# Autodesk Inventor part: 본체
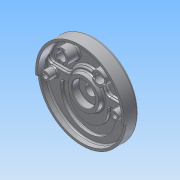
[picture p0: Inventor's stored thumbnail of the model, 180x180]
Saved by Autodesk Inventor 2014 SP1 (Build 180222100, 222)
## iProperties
Created: 2015-05
Part Number: 본체
Material: 알루미늄 6061
Document SubType Name: Modeling
Designer: 상담실
Density: 2.71 g/cm^3
Appearance: 알루미늄 - 평지
Mass: 1082.91 g
Surface Area: 1042.06 cm^2
Volume: 399.598 cm^3
Author: 상담실
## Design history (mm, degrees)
sketch "스케치1"
  geometry: C1 r 95 at (0, 0); 1 further point
  constraints: 1 centre point, 1 coincident
  dimensions: "d0" = 190 diameter of C1
extrude "돌출1" new body sketch "스케치1" distance "d1" = 32; taper "d2" = 0 deg
sketch "스케치2"
  geometry: C1 r 95 at (0, 0) reference; C2 r 90 at (0, 0)
  constraints: 1 centre point, 1 coincident
  dimensions: "d3" = 180 diameter of C2
extrude "돌출2" cut sketch "스케치2" distance "d4" = 25; taper "d5" = 0 deg
sketch "스케치3"
  geometry: L1 (-94.638, -8.28)-(-89.658, -7.844); L2 (89.658, -7.844)-(94.638, -8.28); L3 (-95, 0)-(95, 0); A1 r 90 centre (0, 0) between (-89.658, -7.844) and (89.658, -7.844) reference; A2 r 95 centre (0, 0) between (-94.638, -8.28) and (94.638, -8.28) reference; 2 further points
  constraints: 6 end point, 6 point on circle, 2 midpoint, 2 point on line, 1 coincident, 1 horizontal
  dimensions: "d6" = 5 deg angle of L3 L1; "d7" = 5 deg angle of L2 L3
extrude "돌출3" cut sketch "스케치3" distance "d8" = 5; taper "d9" = 0 deg
sketch "스케치4"
  geometry: L1 (-89.196, 12)-(-40.249, 12); L2 (40.249, 12)-(89.196, 12); A1 r 90 centre (0, 0) between (-89.196, 12) and (89.196, 12) reference; A2 r 42 centre (0, 0) between (40.249, 12) and (-40.249, 12)
  constraints: 4 end point, 4 point on circle, 2 horizontal, 1 centre point, 1 coincident, 1 collinear
  dimensions: "d10" = 84 diameter of A2; "d11" = 12 distance from line of A1.centre L1
extrude "돌출4" join sketch "스케치4" distance "d12" = 7; taper "d13" = 0 deg
sketch "스케치5"
  geometry: C1 r 35 at (0, 0); A1 r 42 centre (0, 0) between (40.249, 12) and (-40.249, 12) reference
  constraints: 1 centre point, 1 coincident
  dimensions: "d14" = 70 diameter of C1
extrude "돌출5" join sketch "스케치5" distance "d15" = 10; taper "d16" = -10 deg
sketch "스케치6"
  geometry: C1 r 95 at (0, 0) reference; C2 r 25 at (0, 0)
  constraints: 1 centre point, 1 coincident
  dimensions: "d17" = 50 diameter of C2
extrude "돌출6" join sketch "스케치6" distance "d18" = 12; taper "d19" = -15 deg
hole "구멍1" diameter "d22" = 23; stored, may be unused: countersink angle "d26" = 90 deg, drill point angle "d28" = 118 deg; dims "d20" = 10, "d21" = 10, "d23" = 6, "d24" = 4, "d25" = 2, "d27" = 8
fillet "모깎기1" dims "d31" = 10
fillet "모깎기2" dims "d32" = 3
fillet "모깎기3" dims "d33" = 5
sketch "스케치7"
  geometry: C1 r 9 at (-74, 0); C2 r 9 at (74, 0); A1 r 87 centre (0, 0) between (-86.059, 12.759) and (86.059, 12.759) reference
  constraints: 2 centre point, 2 horizontal alignment
  dimensions: "d34" = 18 diameter of C1; "d35" = 18 diameter of C2; "d36" = 148 distance of C2.centre C1.centre; "d37" = 74 distance of A1.centre C1.centre (= 0.5 x d36)
extrude "돌출7" join sketch "스케치7" distance "d38" = 18; taper "d39" = 0 deg
hole "구멍2" diameter "d42" = 11; stored, may be unused: countersink angle "d46" = 90 deg, drill point angle "d48" = 118 deg; dims "d40" = 10, "d41" = 10, "d43" = 6, "d44" = 4, "d45" = 2, "d47" = 8
hole "구멍3" diameter "d51" = 11; stored, may be unused: countersink angle "d55" = 90 deg, drill point angle "d57" = 118 deg; dims "d49" = 10, "d50" = 10, "d52" = 6, "d53" = 4, "d54" = 2, "d56" = 8
hole "구멍4" diameter "d60" = 18; stored, may be unused: countersink angle "d64" = 90 deg, drill point angle "d66" = 0 deg; dims "d61" = 6, "d62" = 4, "d63" = 2, "d65" = 11, "d67" = 10, "d68" = 10
hole "구멍5" diameter "d71" = 18; stored, may be unused: countersink angle "d75" = 90 deg, drill point angle "d77" = 0 deg; dims "d69" = 10, "d70" = 10, "d72" = 6, "d73" = 4, "d74" = 2, "d76" = 11
sketch "스케치8"
  geometry: C1 r 15 at (-40, 52); C2 r 15 at (40, 52); A1 r 45 centre (0, 0) between (40.774, 19.038) and (-40.774, 19.038) reference
  constraints: 2 centre point, 1 horizontal alignment
  dimensions: "d78" = 30 diameter of C1; "d79" = 30 diameter of C2; "d80" = 52 vertical distance of A1.centre C1.centre; "d81" = 80 distance of C2.centre C1.centre; "d82" = 40 horizontal distance of A1.centre C1.centre (= 0.5 x d81)
extrude "돌출8" join sketch "스케치8" distance "d83" = 25; taper "d84" = 0 deg
hole "구멍6" diameter "d87" = 20; stored, may be unused: countersink angle "d91" = 90 deg, drill point angle "d93" = 0 deg; dims "d85" = 10, "d86" = 10, "d88" = 6, "d89" = 4, "d90" = 2, "d92" = 11
hole "구멍7" diameter "d96" = 20; stored, may be unused: countersink angle "d100" = 90 deg, drill point angle "d102" = 0 deg; dims "d94" = 10, "d95" = 10, "d97" = 6, "d98" = 4, "d99" = 2, "d101" = 11
sketch "스케치9"
  geometry: L1 (-6, -15)-(6, -15); L2 (6, -15)-(6, 15); L3 (6, 15)-(-6, 15); L4 (-6, 15)-(-6, -15); L5 (-6, -15)-(6, 15); L6 (6, -15)-(-6, 15); L7 (65, -6)-(95, -6); L8 (95, -6)-(95, 6); L9 (95, 6)-(65, 6); L10 (65, 6)-(65, -6); L11 (65, -6)-(95, 6); L12 (95, -6)-(65, 6); C1 r 15 at (0, 0) reference; C2 r 10 at (80, 0) reference; 1 further point
  constraints: 24 end point, 4 midpoint, 4 parallel, 2 horizontal, 2 perpendicular
  dimensions: "d103" = 12 distance of L3.end L2.end; "d104" = 30 distance of L2.end L1.end; "d105" = 30 distance of L9.end L8.end; "d106" = 12 distance of L8.end L7.end
extrude "돌출9" cut sketch "스케치9" distance "d107" = 3; taper "d108" = 0 deg
sketch "스케치10"
  geometry: L1 (-76.916, 9)-(-74, 9) reference; L2 (-59, -19)-(-41, -19); L3 (41, -19)-(59, -19); L4 (-59, -19)-(-59, -14); L5 (-41, -14)-(-41, -19); L6 (41, -19)-(41, -14); L7 (59, -14)-(59, -19); C1 r 37.517 at (0, 0) reference; A1 r 59 centre (0, -19) between (-59, -19) and (59, -19); A2 r 41 centre (0, -19) between (-41, -19) and (41, -19); A3 r 9 centre (-50, -14) between (-41, -14) and (-59, -14); A4 r 9 centre (50, -14) between (59, -14) and (41, -14); 2 further points
  constraints: 12 end point, 8 point on circle, 8 tangent, 5 parallel, 4 centre point, 3 coincident, 1 horizontal alignment, 1 perpendicular, 1 vertical alignment
  dimensions: "d110" = 118 diameter of A1; "d111" = 82 diameter of A2; "d112" = 19 distance of C1.centre A1.centre; "d114" = 5 vertical distance of A1.centre A3.centre
extrude "돌출10" cut sketch "스케치10" distance "d115" = 7; taper "d116" = 0 deg
hole "구멍8" diameter "d119" = 50; stored, may be unused: countersink angle "d123" = 90 deg, drill point angle "d125" = 0 deg; dims "d117" = 10, "d118" = 10, "d120" = 6, "d121" = 4, "d122" = 2, "d124" = 15
chamfer "모따기1" distance "d126" = 1; stored, may be unused: second distance "d127" = 2, angle "d128" = 45 deg
sketch "스케치11"
  geometry: L1 (95, 0)-(-95, 0); L2 (47.244, 47.244)-(39.44, 39.44); L3 (-39.44, 39.44)-(-47.244, 47.244); C1 r 25 at (0, 0) reference; C2 r 90 at (0, 0) reference; A1 r 51 centre (0, 0) between (32.699, 39.138) and (-32.699, 39.138); A2 r 72 centre (0, 0) between (46.97, 54.569) and (-46.97, 54.569); A3 r 5 centre (-43.709, 50.78) between (-46.97, 54.569) and (-47.244, 47.244); A4 r 5 centre (-35.904, 42.975) between (-39.44, 39.44) and (-32.699, 39.138); A5 r 5 centre (35.904, 42.975) between (32.699, 39.138) and (39.44, 39.44); A6 r 5 centre (43.709, 50.78) between (47.244, 47.244) and (46.97, 54.569); 5 further points
  constraints: 16 point on circle, 8 tangent, 6 centre point, 6 end point, 6 point on line, 3 coincident, 3 equal radius, 1 horizontal, 1 midpoint
  dimensions: "d130" = 102 diameter of A1; "d131" = 190 distance of L1.start L1.end; "d133" = 45 deg angle of L2 L1; "d134" = 45 deg angle of L3 L1; "d135" = 72 radius of A2; "d144" = 5 radius of A3
extrude "돌출11" join sketch "스케치11" distance "d136" = 5; taper "d137" = 0 deg
fillet "모깎기6" dims "d143" = 3
fillet "모깎기7" dims "d145" = 5, "d146" = 3
sketch "스케치13"
  geometry: C1 r 68 at (0, 0); A1 r 67 centre (0, 0) between (43.709, 50.78) and (-43.709, 50.78) reference
  constraints: 1 centre point, 1 coincident, 1 other
  dimensions: "d147" = 136 diameter of C1
feature "엠보싱2" sketch "스케치13" dims "d0" = 190, "d8" = 5, "d9" = 0, "d148" = 0.5, "d149" = 0
fillet "모깎기8" dims "d150" = 0.3
fillet "모깎기9" dims "d151" = 3
fillet "모깎기10" dims "d152" = 1
fillet "모깎기11" dims "d153" = 3
fillet "모깎기12" dims "d154" = 3
node "솔리드1"
other parameters: "d129" = 144, "d132" = 72
